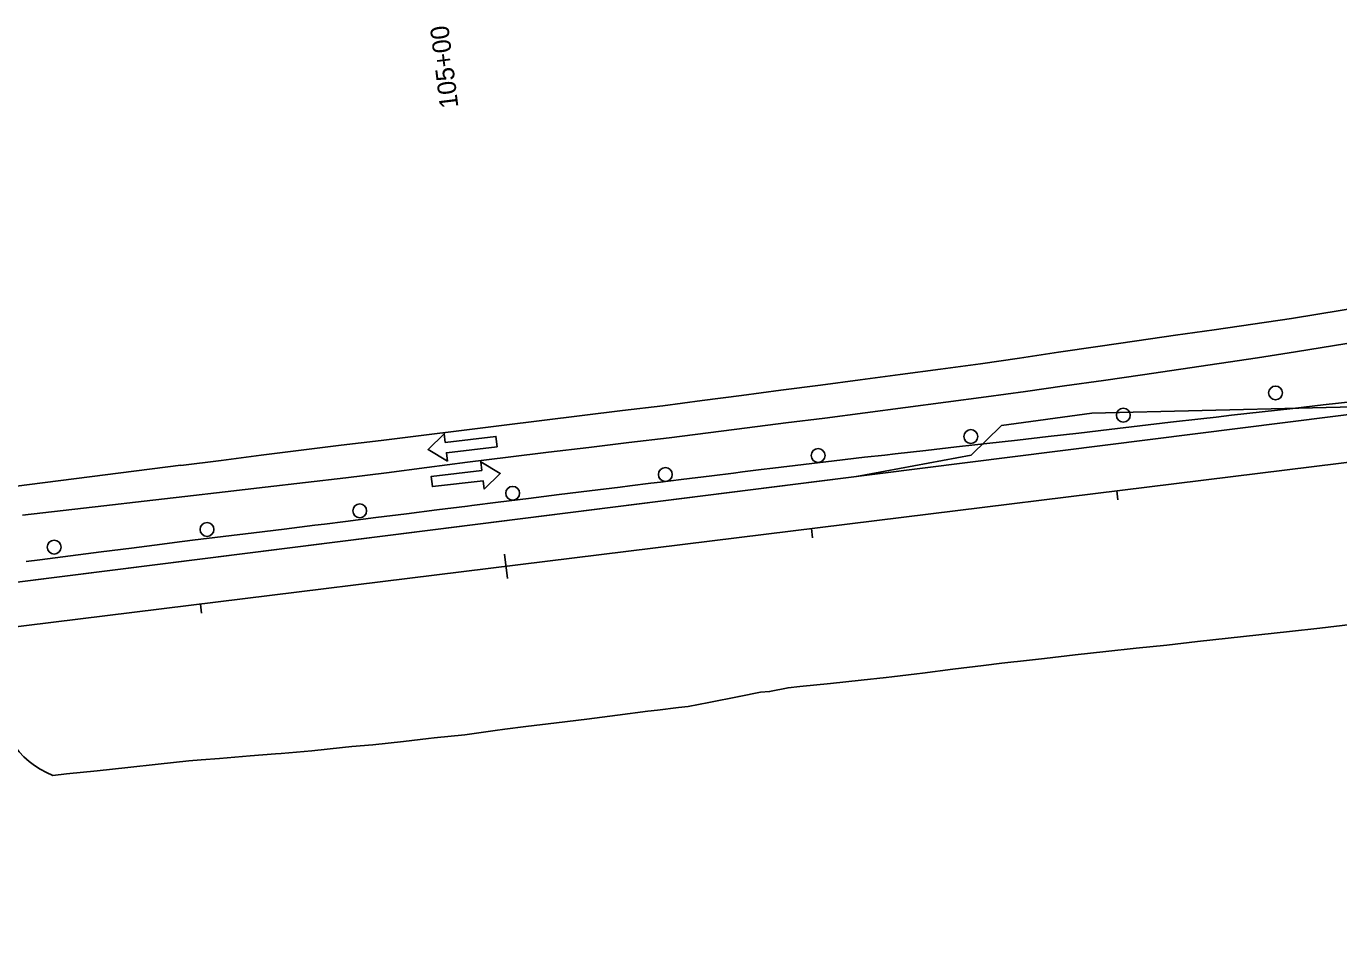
# Model space of a CAD drawing. Extents: x 1568809 to 1572786, y 728326 to 734907.
# Drawn here: x 1570626.7 to 1571053.2, y 732119 to 732419.2 of the extents above; entities that cross this region are included whole.
import ezdxf

# ---------------------------------------------------------------- set-up
doc = ezdxf.new("R2010")
doc.units = 0
for name, color, linetype in [('R_Horz Alg', 7, 'Continuous'), ('R_Horz Alg Annot', 7, 'Continuous'), ('R_MOT', 7, 'Continuous'), ('R_No Plot', 7, 'Continuous'), ('R_Proposed Const Limits_Fill', 7, 'Continuous'), ('R_Striping', 7, 'Continuous')]:
    doc.layers.add(name, color=color, linetype=linetype)

msp = doc.modelspace()

# ---------------------------------------------------------------- linework, layer by layer
at = {"layer": 'R_Horz Alg'}
msp.add_line((1569774.69, 732119.01), (1571082.41, 732280.73), dxfattribs=at)
at = {"layer": 'R_Horz Alg Annot'}
for points in [[(1570981.47, 732265.23), (1570981.1, 732268.21)], [(1570882.23, 732252.95), (1570881.86, 732255.93)], [(1570782.13, 732247.63), (1570783.11, 732239.69)], [(1570683.74, 732228.41), (1570683.37, 732231.38)]]:
    msp.add_lwpolyline(points, dxfattribs=at)
at = {"layer": 'R_MOT'}
for points in [[(1570763.62, 732277.78), (1570757.3, 732281.56), (1570762.57, 732286.72), (1570762.9, 732283.93), (1570779.33, 732285.87), (1570779.73, 732282.52), (1570763.29, 732280.58)], [(1570775.49, 732268.69), (1570780.76, 732273.85), (1570774.43, 732277.63), (1570774.76, 732274.84), (1570758.32, 732272.89), (1570758.72, 732269.54), (1570775.16, 732271.48)]]:
    msp.add_lwpolyline(points, close=True, dxfattribs=at)
for centre in [(1571032.68, 732300), (1570983.2, 732292.78), (1570933.65, 732285.81), (1570884.03, 732279.66), (1570834.41, 732273.5), (1570784.79, 732267.38), (1570735.1, 732261.68), (1570685.48, 732255.63), (1570635.8, 732249.89)]:
    msp.add_circle(centre, 2.25, dxfattribs=at)
at = {"layer": 'R_No Plot'}
for points in [[(1571080.52, 732296.05), (1570444.72, 732215.92), (1570431.22, 732213.94), (1570302.77, 732199.43)], [(1571080.52, 732296.05), (1570973.02, 732293.44), (1570943.63, 732289.39), (1570933.75, 732279.73), (1570896.54, 732272.86), (1570444.72, 732215.92), (1570431.22, 732213.94), (1570302.77, 732199.43)], [(1570626.75, 732245.23), (1570631.21, 732245.78), (1570641.13, 732247.04), (1570651.05, 732248.3), (1570660.97, 732249.56), (1570670.89, 732250.83), (1570674.89, 732251.34), (1570680.81, 732252.1), (1570690.74, 732253.31), (1570700.66, 732254.53), (1570710.59, 732255.76), (1570720.51, 732256.99), (1570723.64, 732257.38), (1570730.43, 732258.24), (1570740.36, 732259.48), (1570750.28, 732260.73), (1570760.2, 732261.98), (1570770.12, 732263.23), (1570771.57, 732263.42), (1570780.04, 732264.5), (1570789.96, 732265.73), (1570799.89, 732266.95), (1570809.81, 732268.17), (1570819.74, 732269.41), (1570822.86, 732269.79), (1570829.66, 732270.64), (1570832.79, 732271.03), (1570839.58, 732271.87), (1570849.51, 732273.1), (1570856.54, 732273.97), (1570859.43, 732274.32), (1570865.54, 732275.06), (1570869.36, 732275.54), (1570879.28, 732276.78), (1570889.21, 732277.97), (1570899.15, 732279.08), (1570905.76, 732279.81), (1570909.09, 732280.18), (1570919.03, 732281.31), (1570928.96, 732282.43), (1570934.95, 732283.1), (1570938.9, 732283.55), (1570948.84, 732284.68), (1570958.78, 732285.81), (1570968.71, 732286.97), (1570978.64, 732288.14), (1570988.57, 732289.32), (1570998.5, 732290.47), (1571008.44, 732291.59), (1571013.38, 732292.16), (1571018.38, 732292.72), (1571028.31, 732293.86), (1571038.25, 732294.97), (1571048.18, 732296.13), (1571058.12, 732297.26)], [(1571058.12, 732297.26), (1571048.18, 732296.13), (1571038.25, 732294.97), (1571028.31, 732293.86), (1571018.38, 732292.72), (1571013.38, 732292.16), (1571008.44, 732291.59), (1570998.5, 732290.47), (1570988.57, 732289.32), (1570978.64, 732288.14), (1570968.71, 732286.97), (1570958.78, 732285.81), (1570948.84, 732284.68), (1570938.9, 732283.55), (1570934.95, 732283.1), (1570928.96, 732282.43), (1570919.03, 732281.31), (1570909.09, 732280.18), (1570905.76, 732279.81), (1570899.15, 732279.08), (1570889.21, 732277.97), (1570879.28, 732276.78), (1570869.36, 732275.54), (1570865.54, 732275.06), (1570859.43, 732274.32), (1570856.54, 732273.97), (1570849.51, 732273.1), (1570839.58, 732271.87), (1570832.79, 732271.03), (1570829.66, 732270.64), (1570822.86, 732269.79), (1570819.74, 732269.41), (1570809.81, 732268.17), (1570799.89, 732266.95), (1570789.96, 732265.73), (1570780.04, 732264.5), (1570771.57, 732263.42), (1570770.12, 732263.23), (1570760.2, 732261.98), (1570750.28, 732260.73), (1570740.36, 732259.48), (1570730.43, 732258.24), (1570723.64, 732257.38), (1570720.51, 732256.99), (1570710.59, 732255.76), (1570700.66, 732254.53), (1570690.74, 732253.31), (1570680.81, 732252.1), (1570674.89, 732251.34), (1570670.89, 732250.83), (1570660.97, 732249.56), (1570651.05, 732248.3), (1570641.13, 732247.04), (1570631.21, 732245.78), (1570626.75, 732245.23)], [(1571057.02, 732224.69), (1571047.08, 732223.57), (1571037.15, 732222.42), (1571027.2, 732221.36), (1571022.21, 732220.82), (1571017.26, 732220.28), (1571007.32, 732219.18), (1570997.38, 732218.05), (1570987.43, 732217.02), (1570977.49, 732215.98), (1570967.55, 732214.87), (1570957.61, 732213.73), (1570948.82, 732212.71), (1570947.68, 732212.58), (1570943.73, 732212.12), (1570937.75, 732211.42), (1570927.83, 732210.16), (1570917.91, 732208.87), (1570916.07, 732208.65), (1570907.98, 732207.71), (1570906.14, 732207.49), (1570898.03, 732206.65), (1570888.09, 732205.57), (1570878.14, 732204.57), (1570874.3, 732204.19), (1570868.27, 732202.91), (1570865.34, 732202.73), (1570858.38, 732201.36), (1570848.54, 732199.42), (1570841.81, 732198.08), (1570838.67, 732197.78), (1570831.88, 732196.89), (1570828.75, 732196.51), (1570818.82, 732195.31), (1570808.91, 732194.01), (1570798.98, 732192.79), (1570789.06, 732191.55), (1570782.26, 732190.7), (1570779.14, 732190.27), (1570769.24, 732188.89), (1570759.28, 732187.92), (1570757.45, 732187.69), (1570749.36, 732186.67), (1570739.41, 732185.65), (1570732.58, 732185.04), (1570729.45, 732184.71), (1570719.5, 732183.71), (1570709.53, 732182.85), (1570707.68, 732182.71), (1570699.55, 732182.05), (1570689.58, 732181.22), (1570683.62, 732180.71), (1570679.61, 732180.37), (1570669.66, 732179.32), (1570659.71, 732178.26), (1570649.77, 732177.21), (1570639.82, 732176.16), (1570635.41, 732175.7)], [(1570635.41, 732175.7), (1570639.82, 732176.16), (1570649.77, 732177.21), (1570659.71, 732178.26), (1570669.66, 732179.32), (1570679.61, 732180.37), (1570683.62, 732180.71), (1570689.58, 732181.22), (1570699.55, 732182.05), (1570707.68, 732182.71), (1570709.53, 732182.85), (1570719.5, 732183.71), (1570729.45, 732184.71), (1570732.58, 732185.04), (1570739.41, 732185.65), (1570749.36, 732186.67), (1570757.45, 732187.69), (1570759.28, 732187.92), (1570769.24, 732188.89), (1570779.14, 732190.27), (1570782.26, 732190.7), (1570789.06, 732191.55), (1570798.98, 732192.79), (1570808.91, 732194.01), (1570818.82, 732195.31), (1570828.75, 732196.51), (1570831.88, 732196.89), (1570838.67, 732197.78), (1570841.81, 732198.08), (1570848.54, 732199.42), (1570858.38, 732201.36), (1570865.34, 732202.73), (1570868.27, 732202.91), (1570874.3, 732204.19), (1570878.14, 732204.57), (1570888.09, 732205.57), (1570898.03, 732206.65), (1570906.14, 732207.49), (1570907.98, 732207.71), (1570916.07, 732208.65), (1570917.91, 732208.87), (1570927.83, 732210.16), (1570937.75, 732211.42), (1570943.73, 732212.12), (1570947.68, 732212.58), (1570948.82, 732212.71), (1570957.61, 732213.73), (1570967.55, 732214.87), (1570977.49, 732215.98), (1570987.43, 732217.02), (1570997.38, 732218.05), (1571007.32, 732219.18), (1571017.26, 732220.28), (1571022.21, 732220.82), (1571027.2, 732221.36), (1571037.15, 732222.42), (1571047.08, 732223.57), (1571057.02, 732224.69)]]:
    msp.add_lwpolyline(points, dxfattribs=at)
msp.add_arc((1570645.26, 732201.4), 27.52, 174.6978, 249.0333, dxfattribs=at)
msp.add_arc((1570645.26, 732201.4), 27.52, 174.6978, 249.0333, dxfattribs=at)
at = {"layer": 'R_Proposed Const Limits_Fill'}
msp.add_lwpolyline([(1570626.75, 732245.23), (1570631.21, 732245.78), (1570641.13, 732247.04), (1570651.05, 732248.3), (1570660.97, 732249.56), (1570670.89, 732250.83), (1570674.89, 732251.34), (1570680.81, 732252.1), (1570690.74, 732253.31), (1570700.66, 732254.53), (1570710.59, 732255.76), (1570720.51, 732256.99), (1570723.64, 732257.38), (1570730.43, 732258.24), (1570740.36, 732259.48), (1570750.28, 732260.73), (1570760.2, 732261.98), (1570770.12, 732263.23), (1570771.57, 732263.42), (1570780.04, 732264.5), (1570789.96, 732265.73), (1570799.89, 732266.95), (1570809.81, 732268.17), (1570819.74, 732269.41), (1570822.86, 732269.79), (1570829.66, 732270.64), (1570832.79, 732271.03), (1570839.58, 732271.87), (1570849.51, 732273.1), (1570856.54, 732273.97), (1570859.43, 732274.32), (1570865.54, 732275.06), (1570869.36, 732275.54), (1570879.28, 732276.78), (1570889.21, 732277.97), (1570899.15, 732279.08), (1570905.76, 732279.81), (1570909.09, 732280.18), (1570919.03, 732281.31), (1570928.96, 732282.43), (1570934.95, 732283.1), (1570938.9, 732283.55), (1570948.84, 732284.68), (1570958.78, 732285.81), (1570958.78, 732285.81), (1570968.71, 732286.97), (1570978.64, 732288.14), (1570988.57, 732289.32), (1570998.5, 732290.47), (1571008.44, 732291.59), (1571013.38, 732292.16), (1571018.38, 732292.72), (1571028.31, 732293.86), (1571038.25, 732294.97), (1571048.18, 732296.13), (1571058.12, 732297.26)], dxfattribs=at)
at = {"layer": 'R_Striping'}
for points in [[(1570603.18, 732267.13), (1570627.78, 732270.25), (1570652.38, 732273.37), (1570676.98, 732276.49), (1570677.02, 732276.46), (1570690.04, 732278.09), (1570703.06, 732279.72), (1570716.07, 732281.35), (1570729.09, 732282.97), (1570742.1, 732284.58), (1570755.11, 732286.19), (1570768.12, 732287.8), (1570781.13, 732289.41), (1570794.24, 732291.03), (1570807.35, 732292.64), (1570820.46, 732294.25), (1570833.57, 732295.86), (1570846.36, 732297.54), (1570859.16, 732299.21), (1570871.96, 732300.88), (1570884.76, 732302.56), (1570897.75, 732304.29), (1570910.75, 732306.02), (1570923.75, 732307.75), (1570936.75, 732309.48), (1570949.47, 732311.34), (1570962.19, 732313.2), (1570974.92, 732315.05), (1570987.64, 732316.91), (1571000.2, 732318.74), (1571012.76, 732320.56), (1571025.32, 732322.38), (1571037.88, 732324.21), (1571062.21, 732328.15)], [(1570625.54, 732260.22), (1570638.72, 732261.75), (1570651.9, 732263.28), (1570665.07, 732264.81), (1570678.25, 732266.34), (1570691.33, 732267.85), (1570704.41, 732269.35), (1570717.49, 732270.86), (1570730.58, 732272.37), (1570743.76, 732274.07), (1570756.94, 732275.76), (1570770.12, 732277.46), (1570783.3, 732279.16), (1570796.4, 732280.72), (1570809.49, 732282.29), (1570822.59, 732283.86), (1570835.68, 732285.42), (1570848.31, 732287.02), (1570860.95, 732288.62), (1570873.58, 732290.23), (1570886.21, 732291.83), (1570899.33, 732293.55), (1570912.45, 732295.28), (1570925.57, 732297), (1570938.69, 732298.73), (1570951.39, 732300.51), (1570964.09, 732302.29), (1570976.78, 732304.07), (1570989.48, 732305.84), (1571001.91, 732307.71), (1571014.34, 732309.58), (1571026.76, 732311.45), (1571039.19, 732313.32), (1571063.81, 732317.37)]]:
    msp.add_lwpolyline(points, dxfattribs=at)

# ---------------------------------------------------------------- texts
at = {"layer": 'R_Horz Alg Annot'}
msp.add_text('105+00', height=6, rotation=97.05, dxfattribs=at).set_placement((1570767.18, 732392.89))

doc.saveas('drawing.dxf')
